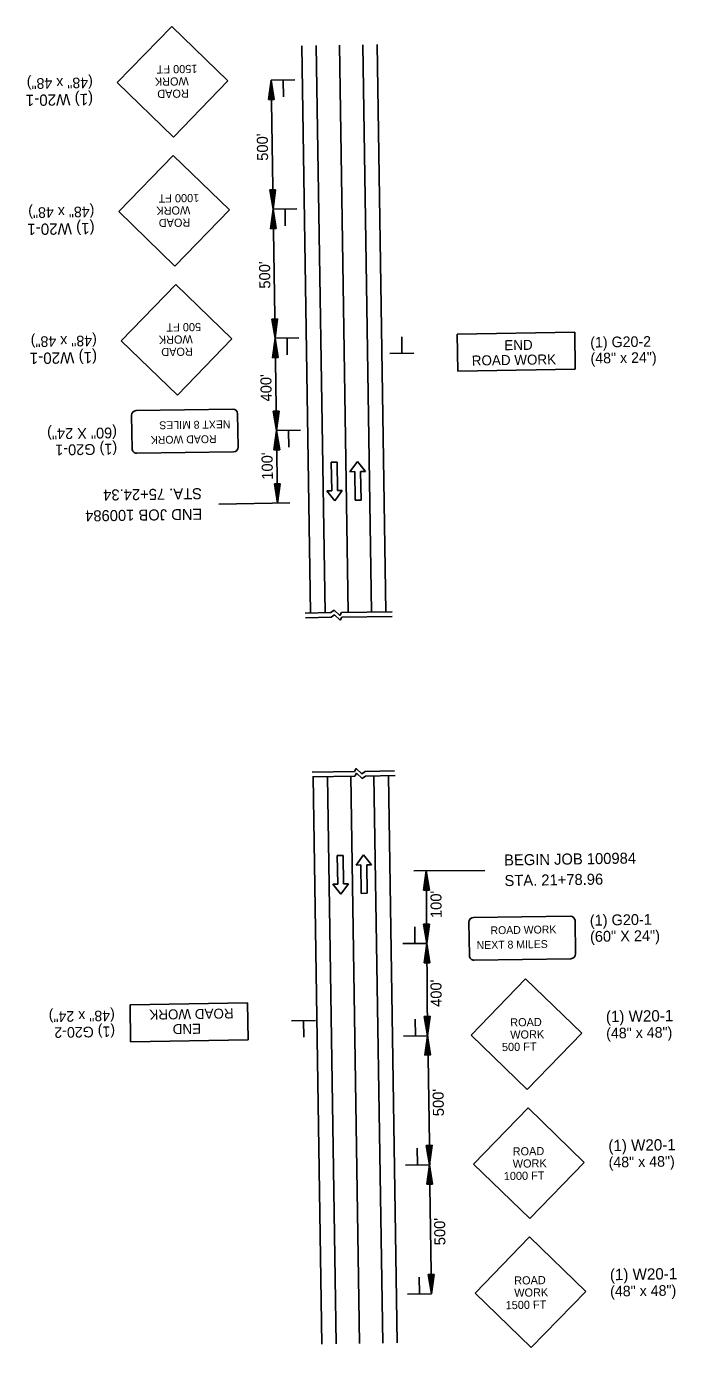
# Model space of a CAD drawing. Extents: x 1770018 to 1773492, y 718230 to 729141.
# Drawn here: x 1771107 to 1771467, y 720575 to 721306 of the extents above; entities that cross this region are included whole.
import ezdxf

# ---------------------------------------------------------------- set-up
doc = ezdxf.new("R2010")
doc.units = 0
for name, color, linetype in [('Default', 7, 'Continuous'), ('R_Dimension', 7, 'Continuous'), ('R_Draft', 7, 'Continuous'), ('R_MOT', 7, 'Continuous')]:
    doc.layers.add(name, color=color, linetype=linetype)

msp = doc.modelspace()

# ---------------------------------------------------------------- linework, layer by layer
at = {"layer": 'Default'}
for p, q in [((1771267.54, 721295.92), (1771272.38, 720981.96)), ((1771280.4, 721296.12), (1771285.24, 720982.16)), ((1771293.26, 721296.32), (1771298.09, 720982.35)), ((1771242.53, 721276.67), (1771243.63, 721205.25)), ((1771243.63, 721205.25), (1771244.73, 721133.83)), ((1771244.73, 721133.83), (1771245.51, 721082.77)), ((1771245.51, 721082.77), (1771246.13, 721042.58)), ((1771275.84, 721065.24), (1771279.05, 721065.29)), ((1771276.08, 721049.48), (1771275.84, 721065.24)), ((1771279.29, 721049.53), (1771279.05, 721065.29)), ((1771286.21, 721060), (1771290.41, 721065.62)), ((1771290.41, 721065.62), (1771294.78, 721060.13)), ((1771286.21, 721060), (1771288.89, 721060.04)), ((1771288.89, 721060.04), (1771289.13, 721044.28)), ((1771292.1, 721060.09), (1771294.78, 721060.13)), ((1771292.1, 721060.09), (1771292.34, 721044.33)), ((1771273.4, 721049.44), (1771276.08, 721049.48)), ((1771273.4, 721049.44), (1771277.77, 721043.94)), ((1771277.77, 721043.94), (1771281.97, 721049.57)), ((1771279.29, 721049.53), (1771281.97, 721049.57)), ((1771213.69, 721042.08), (1771252.97, 721042.69)), ((1771289.13, 721044.28), (1771292.34, 721044.33)), ((1771261.43, 720981.79), (1771275.64, 720982.01)), ((1771261.65, 720979.21), (1771275.86, 720979.43)), ((1771281.51, 720982.1), (1771309.58, 720982.53)), ((1771281.73, 720979.52), (1771309.61, 720979.95)), ((1771288.71, 720894.05), (1771265.27, 720893.69)), ((1771288.94, 720891.48), (1771265.5, 720891.12)), ((1771278.62, 720577.28), (1771273.78, 720891.24)), ((1771291.47, 720577.48), (1771286.64, 720891.44)), ((1771310.93, 720894.4), (1771294.59, 720894.14)), ((1771311.16, 720891.82), (1771294.81, 720891.57)), ((1771304.33, 720577.68), (1771299.49, 720891.64)), ((1771279.19, 720847.57), (1771282.4, 720847.62)), ((1771279.43, 720831.81), (1771279.19, 720847.57)), ((1771282.65, 720831.86), (1771282.4, 720847.62)), ((1771289.56, 720842.33), (1771293.76, 720847.96)), ((1771293.76, 720847.96), (1771298.13, 720842.46)), ((1771289.56, 720842.33), (1771292.24, 720842.37)), ((1771292.24, 720842.37), (1771292.48, 720826.61)), ((1771295.45, 720842.42), (1771298.13, 720842.46)), ((1771295.45, 720842.42), (1771295.7, 720826.66)), ((1771360.91, 720839.34), (1771321.62, 720839.07)), ((1771328.74, 720798.92), (1771328.46, 720839.12)), ((1771276.76, 720831.77), (1771279.43, 720831.81)), ((1771276.76, 720831.77), (1771281.13, 720826.28)), ((1771281.13, 720826.28), (1771285.33, 720831.9)), ((1771282.65, 720831.86), (1771285.33, 720831.9)), ((1771292.48, 720826.61), (1771295.7, 720826.66)), ((1771329.09, 720747.86), (1771328.74, 720798.92)), ((1771330.46, 720676.45), (1771329.36, 720747.87)), ((1771331.29, 720605.02), (1771330.19, 720676.44))]:
    msp.add_line(p, q, dxfattribs=at)
for points in [[(1771281.51, 720982.1), (1771280.55, 720980.43), (1771277.46, 720983.33), (1771275.64, 720982.01)], [(1771281.73, 720979.52), (1771280.77, 720977.85), (1771277.69, 720980.76), (1771275.86, 720979.43)], [(1771288.71, 720894.05), (1771289.67, 720895.72), (1771292.76, 720892.82), (1771294.59, 720894.14)], [(1771288.94, 720891.48), (1771289.89, 720893.14), (1771292.98, 720890.24), (1771294.81, 720891.57)]]:
    msp.add_lwpolyline(points, dxfattribs=at)
at = {"layer": 'R_Dimension'}
for p, q in [((1771259.55, 721295.8), (1771264.38, 720981.83)), ((1771301.26, 721296.44), (1771306.09, 720982.48)), ((1771270.62, 720577.16), (1771265.78, 720891.12)), ((1771312.33, 720577.8), (1771307.49, 720891.76))]:
    msp.add_line(p, q, dxfattribs=at)
at = {"layer": 'R_Draft'}
for p, q in [((1771241.09, 721265.93), (1771242.53, 721276.67)), ((1771244.3, 721265.98), (1771242.53, 721276.67)), ((1771241.35, 721265.93), (1771242.55, 721274.88)), ((1771241.63, 721265.94), (1771242.58, 721273.04)), ((1771241.89, 721265.94), (1771242.61, 721271.25)), ((1771242.17, 721265.95), (1771242.64, 721269.44)), ((1771244.03, 721265.98), (1771242.55, 721274.88)), ((1771243.76, 721265.97), (1771242.58, 721273.04)), ((1771243.49, 721265.97), (1771242.61, 721271.25)), ((1771243.22, 721265.96), (1771242.64, 721269.44)), ((1771241.09, 721265.93), (1771244.3, 721265.98)), ((1771242.44, 721265.95), (1771242.67, 721267.65)), ((1771242.94, 721265.96), (1771242.67, 721267.65)), ((1771245.07, 721215.99), (1771241.86, 721215.94)), ((1771241.86, 721215.94), (1771243.63, 721205.25)), ((1771242.12, 721215.94), (1771243.6, 721207.04)), ((1771242.4, 721215.94), (1771243.57, 721208.88)), ((1771242.66, 721215.95), (1771243.54, 721210.66)), ((1771242.94, 721215.95), (1771243.52, 721212.48)), ((1771243.21, 721215.96), (1771243.49, 721214.27)), ((1771243.71, 721215.96), (1771243.49, 721214.27)), ((1771243.98, 721215.97), (1771243.52, 721212.48)), ((1771244.26, 721215.97), (1771243.54, 721210.66)), ((1771244.53, 721215.98), (1771243.57, 721208.88)), ((1771244.8, 721215.98), (1771243.6, 721207.04)), ((1771245.07, 721215.99), (1771243.63, 721205.25)), ((1771242.19, 721194.51), (1771243.63, 721205.25)), ((1771242.45, 721194.51), (1771243.66, 721203.46)), ((1771245.4, 721194.56), (1771243.63, 721205.25)), ((1771245.13, 721194.56), (1771243.66, 721203.46)), ((1771242.73, 721194.52), (1771243.68, 721201.62)), ((1771242.99, 721194.52), (1771243.71, 721199.83)), ((1771243.27, 721194.53), (1771243.74, 721198.02)), ((1771243.54, 721194.53), (1771243.77, 721196.23)), ((1771244.86, 721194.55), (1771243.68, 721201.62)), ((1771244.59, 721194.55), (1771243.71, 721199.83)), ((1771244.32, 721194.54), (1771243.74, 721198.02)), ((1771244.04, 721194.54), (1771243.77, 721196.23)), ((1771242.19, 721194.51), (1771245.4, 721194.56)), ((1771246.17, 721144.57), (1771242.96, 721144.52)), ((1771242.96, 721144.52), (1771244.73, 721133.83)), ((1771243.22, 721144.52), (1771244.7, 721135.62)), ((1771243.5, 721144.52), (1771244.67, 721137.46)), ((1771243.76, 721144.53), (1771244.64, 721139.24)), ((1771244.04, 721144.53), (1771244.62, 721141.06)), ((1771244.31, 721144.54), (1771244.59, 721142.85)), ((1771244.81, 721144.54), (1771244.59, 721142.85)), ((1771245.08, 721144.55), (1771244.62, 721141.06)), ((1771245.36, 721144.55), (1771244.64, 721139.24)), ((1771245.63, 721144.56), (1771244.67, 721137.46)), ((1771245.9, 721144.56), (1771244.7, 721135.62)), ((1771246.17, 721144.57), (1771244.73, 721133.83)), ((1771243.29, 721123.09), (1771244.73, 721133.83)), ((1771243.55, 721123.09), (1771244.76, 721132.04)), ((1771243.83, 721123.1), (1771244.78, 721130.2)), ((1771246.5, 721123.14), (1771244.73, 721133.83)), ((1771246.23, 721123.14), (1771244.76, 721132.04)), ((1771245.96, 721123.13), (1771244.78, 721130.2)), ((1771243.29, 721123.09), (1771246.5, 721123.14)), ((1771244.1, 721123.1), (1771244.81, 721128.41)), ((1771244.37, 721123.11), (1771244.84, 721126.6)), ((1771244.64, 721123.11), (1771244.87, 721124.81)), ((1771245.69, 721123.13), (1771244.81, 721128.41)), ((1771245.42, 721123.12), (1771244.84, 721126.6)), ((1771245.14, 721123.12), (1771244.87, 721124.81)), ((1771246.96, 721093.51), (1771243.74, 721093.46)), ((1771243.74, 721093.46), (1771245.51, 721082.77)), ((1771244.01, 721093.47), (1771245.49, 721084.56)), ((1771244.28, 721093.47), (1771245.46, 721086.41)), ((1771244.55, 721093.47), (1771245.43, 721088.19)), ((1771244.82, 721093.48), (1771245.4, 721090.01)), ((1771245.1, 721093.48), (1771245.38, 721091.79)), ((1771245.6, 721093.49), (1771245.38, 721091.79)), ((1771245.87, 721093.49), (1771245.4, 721090.01)), ((1771246.15, 721093.5), (1771245.43, 721088.19)), ((1771246.42, 721093.5), (1771245.46, 721086.41)), ((1771246.69, 721093.51), (1771245.49, 721084.56)), ((1771246.96, 721093.51), (1771245.51, 721082.77)), ((1771244.07, 721072.04), (1771245.51, 721082.77)), ((1771244.34, 721072.04), (1771245.54, 721080.98)), ((1771244.61, 721072.04), (1771245.57, 721079.14)), ((1771247.29, 721072.09), (1771245.51, 721082.77)), ((1771247.02, 721072.08), (1771245.54, 721080.98)), ((1771246.75, 721072.08), (1771245.57, 721079.14)), ((1771244.07, 721072.04), (1771247.29, 721072.09)), ((1771244.88, 721072.05), (1771245.6, 721077.36)), ((1771245.16, 721072.05), (1771245.63, 721075.54)), ((1771245.43, 721072.06), (1771245.65, 721073.75)), ((1771246.48, 721072.07), (1771245.6, 721077.36)), ((1771246.2, 721072.07), (1771245.63, 721075.54)), ((1771245.93, 721072.06), (1771245.65, 721073.75)), ((1771247.58, 721053.32), (1771244.36, 721053.27)), ((1771244.36, 721053.27), (1771246.13, 721042.58)), ((1771244.63, 721053.27), (1771246.11, 721044.37)), ((1771244.9, 721053.28), (1771246.08, 721046.21)), ((1771245.17, 721053.28), (1771246.05, 721048)), ((1771245.44, 721053.29), (1771246.02, 721049.81)), ((1771245.72, 721053.29), (1771245.99, 721051.6)), ((1771246.22, 721053.3), (1771245.99, 721051.6)), ((1771246.49, 721053.3), (1771246.02, 721049.81)), ((1771246.77, 721053.31), (1771246.05, 721048)), ((1771247.03, 721053.31), (1771246.08, 721046.21)), ((1771247.31, 721053.32), (1771246.11, 721044.37)), ((1771247.58, 721053.32), (1771246.13, 721042.58)), ((1771326.93, 720828.39), (1771328.46, 720839.12)), ((1771327.2, 720828.4), (1771328.47, 720837.33)), ((1771330.14, 720828.42), (1771328.46, 720839.12)), ((1771329.88, 720828.41), (1771328.47, 720837.33)), ((1771327.47, 720828.4), (1771328.49, 720835.49)), ((1771327.74, 720828.4), (1771328.5, 720833.7)), ((1771328.02, 720828.4), (1771328.51, 720831.89)), ((1771328.28, 720828.4), (1771328.52, 720830.1)), ((1771329.6, 720828.41), (1771328.49, 720835.49)), ((1771329.33, 720828.41), (1771328.5, 720833.7)), ((1771329.06, 720828.41), (1771328.51, 720831.89)), ((1771328.79, 720828.41), (1771328.52, 720830.1)), ((1771326.93, 720828.39), (1771330.14, 720828.42)), ((1771330.18, 720809.66), (1771326.97, 720809.61)), ((1771326.97, 720809.61), (1771328.74, 720798.92)), ((1771327.24, 720809.62), (1771328.71, 720800.71)), ((1771327.51, 720809.62), (1771328.68, 720802.55)), ((1771327.78, 720809.62), (1771328.66, 720804.34)), ((1771328.05, 720809.63), (1771328.63, 720806.15)), ((1771328.32, 720809.63), (1771328.6, 720807.94)), ((1771328.83, 720809.64), (1771328.6, 720807.94)), ((1771329.09, 720809.64), (1771328.63, 720806.15)), ((1771329.37, 720809.65), (1771328.66, 720804.34)), ((1771329.64, 720809.65), (1771328.68, 720802.55)), ((1771329.91, 720809.66), (1771328.71, 720800.71)), ((1771330.18, 720809.66), (1771328.74, 720798.92)), ((1771327.21, 720788.2), (1771328.74, 720798.92)), ((1771327.47, 720788.2), (1771328.75, 720797.13)), ((1771327.75, 720788.2), (1771328.76, 720795.29)), ((1771328.02, 720788.2), (1771328.78, 720793.51)), ((1771330.42, 720788.22), (1771328.74, 720798.92)), ((1771330.15, 720788.22), (1771328.75, 720797.13)), ((1771329.88, 720788.22), (1771328.76, 720795.29)), ((1771329.61, 720788.21), (1771328.78, 720793.51)), ((1771327.21, 720788.2), (1771330.42, 720788.22)), ((1771328.29, 720788.21), (1771328.79, 720791.69)), ((1771328.56, 720788.21), (1771328.8, 720789.9)), ((1771329.34, 720788.21), (1771328.79, 720791.69)), ((1771329.07, 720788.21), (1771328.8, 720789.9)), ((1771330.53, 720758.6), (1771327.32, 720758.55)), ((1771327.32, 720758.55), (1771329.09, 720747.86)), ((1771327.59, 720758.56), (1771329.06, 720749.65)), ((1771327.86, 720758.56), (1771329.04, 720751.5)), ((1771328.13, 720758.56), (1771329.01, 720753.28)), ((1771328.4, 720758.57), (1771328.98, 720755.1)), ((1771328.67, 720758.57), (1771328.95, 720756.88)), ((1771329.18, 720758.58), (1771328.95, 720756.88)), ((1771329.45, 720758.59), (1771328.98, 720755.1)), ((1771329.72, 720758.59), (1771329.01, 720753.28)), ((1771329.99, 720758.59), (1771329.04, 720751.5)), ((1771330.27, 720758.6), (1771329.06, 720749.65)), ((1771330.53, 720758.6), (1771329.09, 720747.86)), ((1771327.65, 720737.13), (1771329.09, 720747.86)), ((1771327.92, 720737.13), (1771329.12, 720746.08)), ((1771328.19, 720737.13), (1771329.15, 720744.23)), ((1771328.46, 720737.14), (1771329.18, 720742.45)), ((1771330.86, 720737.18), (1771329.09, 720747.86)), ((1771330.6, 720737.17), (1771329.12, 720746.08)), ((1771330.32, 720737.17), (1771329.15, 720744.23)), ((1771330.05, 720737.16), (1771329.18, 720742.45)), ((1771327.65, 720737.13), (1771330.86, 720737.18)), ((1771328.74, 720737.14), (1771329.2, 720740.63)), ((1771329, 720737.15), (1771329.23, 720738.84)), ((1771329.78, 720737.16), (1771329.2, 720740.63)), ((1771329.51, 720737.16), (1771329.23, 720738.84)), ((1771331.63, 720687.18), (1771328.42, 720687.13)), ((1771328.42, 720687.13), (1771330.19, 720676.44)), ((1771328.69, 720687.14), (1771330.16, 720678.23)), ((1771328.96, 720687.14), (1771330.14, 720680.08)), ((1771329.23, 720687.14), (1771330.11, 720681.86)), ((1771329.5, 720687.15), (1771330.08, 720683.68)), ((1771329.78, 720687.15), (1771330.05, 720685.46)), ((1771330.28, 720687.16), (1771330.05, 720685.46)), ((1771330.55, 720687.17), (1771330.08, 720683.68)), ((1771330.83, 720687.17), (1771330.11, 720681.86)), ((1771331.09, 720687.17), (1771330.14, 720680.08)), ((1771331.37, 720687.18), (1771330.16, 720678.23)), ((1771331.63, 720687.18), (1771330.19, 720676.44)), ((1771328.75, 720665.71), (1771330.19, 720676.44)), ((1771331.96, 720665.76), (1771330.19, 720676.44)), ((1771329.02, 720665.71), (1771330.22, 720674.66)), ((1771329.29, 720665.71), (1771330.25, 720672.81)), ((1771329.56, 720665.72), (1771330.28, 720671.03)), ((1771329.84, 720665.72), (1771330.3, 720669.21)), ((1771331.7, 720665.75), (1771330.22, 720674.66)), ((1771331.42, 720665.75), (1771330.25, 720672.81)), ((1771331.16, 720665.74), (1771330.28, 720671.03)), ((1771330.88, 720665.74), (1771330.3, 720669.21)), ((1771328.75, 720665.71), (1771331.96, 720665.76)), ((1771330.11, 720665.73), (1771330.33, 720667.42)), ((1771330.61, 720665.73), (1771330.33, 720667.42)), ((1771332.73, 720615.76), (1771329.52, 720615.71)), ((1771329.52, 720615.71), (1771331.29, 720605.02)), ((1771329.79, 720615.72), (1771331.26, 720606.81)), ((1771330.06, 720615.72), (1771331.24, 720608.66)), ((1771330.33, 720615.72), (1771331.21, 720610.44)), ((1771330.6, 720615.73), (1771331.18, 720612.26)), ((1771330.88, 720615.73), (1771331.15, 720614.04)), ((1771331.38, 720615.74), (1771331.15, 720614.04)), ((1771331.65, 720615.75), (1771331.18, 720612.26)), ((1771331.93, 720615.75), (1771331.21, 720610.44)), ((1771332.19, 720615.75), (1771331.24, 720608.66)), ((1771332.47, 720615.76), (1771331.26, 720606.81)), ((1771332.73, 720615.76), (1771331.29, 720605.02))]:
    msp.add_line(p, q, dxfattribs=at)
at = {"layer": 'R_MOT'}
for p, q in [((1771157.38, 721275.36), (1771187.56, 721306.45)), ((1771187.56, 721306.45), (1771218.68, 721276.3)), ((1771188.5, 721245.18), (1771218.68, 721276.3)), ((1771255.76, 721276.87), (1771242.53, 721276.67)), ((1771249.18, 721276.58), (1771249.32, 721267.54)), ((1771157.38, 721275.36), (1771188.5, 721245.18)), ((1771158.22, 721203.93), (1771188.39, 721235.03)), ((1771188.39, 721235.03), (1771219.51, 721204.88)), ((1771158.22, 721203.93), (1771189.33, 721173.76)), ((1771189.33, 721173.76), (1771219.51, 721204.88)), ((1771256.86, 721205.45), (1771243.63, 721205.25)), ((1771250.28, 721205.16), (1771250.42, 721196.12)), ((1771159.58, 721132.52), (1771189.76, 721163.61)), ((1771189.76, 721163.61), (1771220.88, 721133.46)), ((1771410.6, 721137.19), (1771345.51, 721136.19)), ((1771410.91, 721116.74), (1771410.6, 721137.19)), ((1771159.58, 721132.52), (1771190.7, 721102.34)), ((1771190.7, 721102.34), (1771220.88, 721133.46)), ((1771257.96, 721134.03), (1771244.73, 721133.83)), ((1771251.38, 721133.74), (1771251.52, 721124.7)), ((1771314.96, 721125.68), (1771314.82, 721134.71)), ((1771345.82, 721115.74), (1771345.51, 721136.19)), ((1771321.55, 721125.59), (1771308.31, 721125.39)), ((1771410.91, 721116.74), (1771345.82, 721115.74)), ((1771167.82, 721093.8), (1771221.4, 721094.62)), ((1771165.28, 721091.17), (1771165.56, 721072.73)), ((1771224.02, 721092.08), (1771224.3, 721073.64)), ((1771258.75, 721082.98), (1771245.51, 721082.77)), ((1771252.17, 721082.68), (1771252.31, 721073.65)), ((1771168.18, 721070.19), (1771221.76, 721071.01)), ((1771322.09, 720799.07), (1771322.03, 720808.1)), ((1771352.31, 720792.19), (1771352.03, 720810.63)), ((1771408.15, 720814.08), (1771354.57, 720813.25)), ((1771411.06, 720793.09), (1771410.77, 720811.54)), ((1771315.5, 720798.83), (1771328.74, 720798.92)), ((1771408.51, 720790.47), (1771354.94, 720789.64)), ((1771383.39, 720779.36), (1771353.21, 720748.24)), ((1771414.51, 720749.18), (1771383.39, 720779.36)), ((1771164.47, 720764.98), (1771229.56, 720765.98)), ((1771164.47, 720764.98), (1771164.79, 720744.53)), ((1771229.56, 720765.98), (1771229.87, 720745.53)), ((1771322.5, 720747.96), (1771322.36, 720756.99)), ((1771267.07, 720756.33), (1771253.84, 720756.13)), ((1771260.49, 720756.04), (1771260.63, 720747)), ((1771164.79, 720744.53), (1771229.87, 720745.53)), ((1771329.09, 720747.86), (1771315.86, 720747.66)), ((1771384.33, 720718.08), (1771353.21, 720748.24)), ((1771414.51, 720749.18), (1771384.33, 720718.08)), ((1771384.75, 720707.94), (1771354.58, 720676.82)), ((1771415.87, 720677.76), (1771384.75, 720707.94)), ((1771323.6, 720676.54), (1771323.46, 720685.57)), ((1771330.19, 720676.44), (1771316.96, 720676.24)), ((1771385.7, 720646.67), (1771354.58, 720676.82)), ((1771415.87, 720677.76), (1771385.7, 720646.67)), ((1771385.59, 720636.52), (1771355.41, 720605.4)), ((1771416.71, 720606.34), (1771385.59, 720636.52)), ((1771324.7, 720605.12), (1771324.56, 720614.15)), ((1771331.29, 720605.02), (1771318.06, 720604.82)), ((1771386.53, 720575.24), (1771355.41, 720605.4)), ((1771416.71, 720606.34), (1771386.53, 720575.24))]:
    msp.add_line(p, q, dxfattribs=at)
for centre, start, end in [((1771167.86, 721091.21), 90.88269, 180.88269), ((1771221.44, 721092.04), 0.88269, 90.88269), ((1771168.14, 721072.77), 180.88269, 270.88269), ((1771221.72, 721073.6), 270.88269, 0.88269), ((1771354.61, 720810.67), 90.88269, 180.88269), ((1771408.19, 720811.5), 0.88269, 90.88269), ((1771354.9, 720792.23), 180.88269, 270.88269), ((1771408.47, 720793.05), 270.88269, 0.88269)]:
    msp.add_arc(centre, 2.58, start, end, dxfattribs=at)

# ---------------------------------------------------------------- texts
at = {"layer": 'Default'}
for s, rotation, p in [("500'", 90.88269, (1771240.91, 721232.12)), ("500'", 90.88269, (1771242.16, 721161.34)), ("400'", 90.88269, (1771242.89, 721098.89)), ("100'", 90.88269, (1771243.55, 721055.59)), ('STA. 75+24.34', 180.88269, (1771204.22, 721050.93)), ('END JOB 100984', 180.88269, (1771204.4, 721039.55)), ('BEGIN JOB 100984', 0.88269, (1771371.57, 720842.03)), ('STA. 21+78.96', 0.88269, (1771371.75, 720830.65)), ("100'", 90.88269, (1771337.02, 720813)), ("400'", 90.88269, (1771337.02, 720763.82)), ("500'", 90.88269, (1771338.22, 720703.33)), ("500'", 90.88269, (1771339.05, 720631.9))]:
    msp.add_text(s, height=6.1, rotation=rotation, dxfattribs=at).set_placement(p)
at = {"layer": 'R_MOT'}
for s, height, rotation, p in [('1500 FT', 4.516, 180.88326, (1771201.7, 721285.23)), ('(48" x 48")', 5.88, 180.88269, (1771143.85, 721278.24)), ('WORK', 4.515, 180.88272, (1771196.93, 721278.37)), ('(1) W20-1', 6.273, 180.88269, (1771143.99, 721269.22)), ('ROAD', 4.516, 180.88314, (1771196.95, 721271.6)), ('1000 FT', 4.516, 180.88326, (1771202.71, 721213.8)), ('(48" x 48")', 5.88, 180.88269, (1771144.69, 721206.82)), ('WORK', 4.515, 180.88272, (1771197.77, 721206.95)), ('(1) W20-1', 6.273, 180.88269, (1771144.83, 721197.79)), ('ROAD', 4.516, 180.88314, (1771197.79, 721200.18)), ('(48" x 48")', 5.88, 180.88269, (1771146.05, 721135.4)), (' 500 FT', 4.516, 180.88326, (1771205.41, 721142.4)), ('WORK', 4.515, 180.88272, (1771199.13, 721135.53)), ('END', 5.557, 0.88269, (1771371.67, 721127.23)), ('(1) G20-2', 5.881, 0.88269, (1771419.23, 721128.68)), ('(1) W20-1', 6.273, 180.88269, (1771146.19, 721126.38)), ('ROAD', 4.516, 180.88314, (1771199.15, 721128.76)), ('ROAD WORK', 5.557, 0.88269, (1771353.66, 721118.74)), ('(48" x 24")', 5.88, 0.88269, (1771419.37, 721119.86)), ('(60" X 24")', 6, 180.88269, (1771157.2, 721084.53)), (' NEXT 8 MILES', 4.3389, 180.88269, (1771221.58, 721088.47)), ('ROAD WORK', 4.339, 180.88269, (1771212.32, 721080.27)), ('(1) G20-1', 6, 180.88269, (1771157.34, 721075.53)), ('(1) G20-1', 6, 0.88269, (1771418.99, 720808.74)), ('ROAD WORK', 4.339, 0.88269, (1771364.02, 720804)), (' NEXT 8 MILES', 4.3389, 0.88269, (1771354.75, 720795.8)), ('(60" X 24")', 6, 0.88269, (1771419.13, 720799.74)), ('(48" x 24")', 5.88, 180.88269, (1771156.01, 720761.85)), ('ROAD WORK', 5.557, 180.88269, (1771221.73, 720762.97)), ('ROAD', 4.516, 0.88314, (1771374.94, 720752.94)), ('(1) W20-1', 6.273, 0.88269, (1771427.9, 720755.32)), ('(1) G20-2', 5.881, 180.88269, (1771156.15, 720753.04)), ('END', 5.557, 180.88269, (1771203.72, 720754.49)), ('WORK', 4.515, 0.88272, (1771374.95, 720746.16)), ('(48" x 48")', 5.88, 0.88269, (1771428.04, 720746.29)), (' 500 FT', 4.516, 0.88326, (1771368.68, 720739.29)), ('ROAD', 4.516, 0.88314, (1771376.3, 720681.52)), ('(1) W20-1', 6.273, 0.88269, (1771429.26, 720683.9)), ('WORK', 4.515, 0.88272, (1771376.32, 720674.75)), ('(48" x 48")', 5.88, 0.88269, (1771429.4, 720674.88)), ('1000 FT', 4.516, 0.88326, (1771371.38, 720667.89)), ('(1) W20-1', 6.273, 0.88269, (1771430.1, 720612.48)), ('ROAD', 4.516, 0.88314, (1771377.14, 720610.1)), ('WORK', 4.515, 0.88272, (1771377.16, 720603.32)), ('(48" x 48")', 5.88, 0.88269, (1771430.24, 720603.45)), ('1500 FT', 4.516, 0.88326, (1771372.39, 720596.47))]:
    msp.add_text(s, height=height, rotation=rotation, dxfattribs=at).set_placement(p)

doc.saveas('drawing.dxf')
